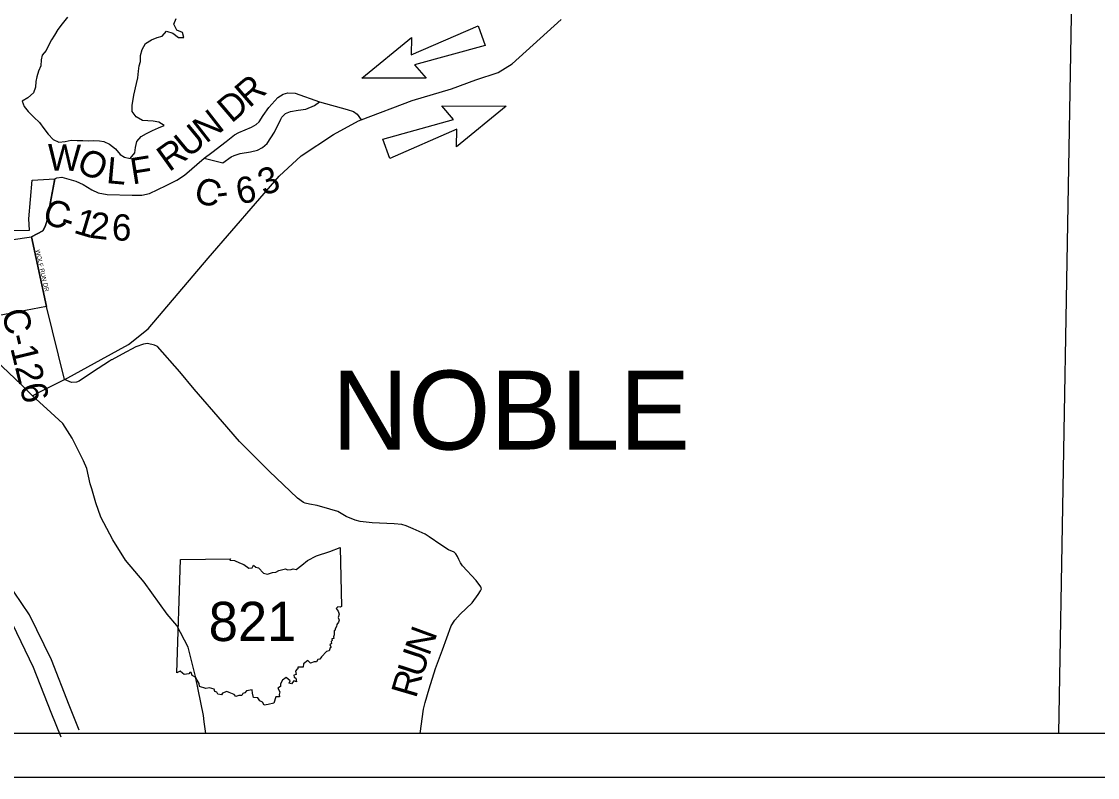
# Model space of a CAD drawing. Extents: x -452339 to 6403467, y -1 to 1814750.
# Drawn here: x -369340 to -357078, y 1603479 to 1612095 of the extents above; entities that cross this region are included whole.
import ezdxf

# ---------------------------------------------------------------- set-up
doc = ezdxf.new("R2010")
doc.units = 0
for name, color, linetype in [('Default', 7, 'Continuous'), ('GM_X_County', 7, 'Continuous'), ('GM_X_County_Road', 7, 'Continuous'), ('GM_X_Major_River', 7, 'Continuous'), ('GM_X_Minor_Lake', 7, 'Continuous'), ('GM_X_Minor_Lake_Text', 7, 'Continuous'), ('GM_X_Minor_River', 7, 'Continuous'), ('GM_X_Minor_River_Text', 7, 'Continuous'), ('GM_X_Section_Text', 7, 'Continuous'), ('GM_X_Township_Subdivision_Text', 7, 'Continuous')]:
    doc.layers.add(name, color=color, linetype=linetype)

msp = doc.modelspace()

# ---------------------------------------------------------------- linework, layer by layer
at = {"layer": 'Default'}
for p, q in [((-364900, 1611714), (-364136, 1612048)), ((-364136, 1612048), (-364057, 1611824)), ((-365463, 1611449), (-364895, 1611915)), ((-364895, 1611915), (-364900, 1611714)), ((-364057, 1611824), (-364860, 1611600)), ((-364860, 1611600), (-364728, 1611448)), ((-364728, 1611448), (-365463, 1611449)), ((-364418, 1610980), (-364550, 1611134)), ((-364550, 1611134), (-363815, 1611132)), ((-363815, 1611132), (-364383, 1610666)), ((-365221, 1610756), (-364418, 1610980)), ((-364379, 1610867), (-365142, 1610533)), ((-364383, 1610666), (-364379, 1610867)), ((-365142, 1610533), (-365221, 1610756)), ((-367572, 1604672), (-367530, 1605963)), ((-345663, 1603979), (-403040, 1603979))]:
    msp.add_line(p, q, dxfattribs=at)
msp.add_lwpolyline([(-403540, 1661857), (-345163, 1661857), (-345163, 1603479), (-403540, 1603479)], close=True, dxfattribs=at)
for points in [[(-367257, 1610538), (-367257, 1610538), (-367170, 1610602), (-367006, 1610728), (-366914, 1610804), (-366864, 1610831), (-366720, 1610893), (-366666, 1610923), (-366632, 1610953), (-366586, 1611025), (-366522, 1611117), (-366420, 1611228), (-366360, 1611266), (-366304, 1611282), (-366220, 1611278), (-365945, 1611179)], [(-367257, 1610538), (-367047, 1610484), (-366952, 1610552), (-366916, 1610568), (-366850, 1610590), (-366732, 1610610), (-366650, 1610629), (-366594, 1610661), (-366542, 1610705), (-366458, 1610833), (-366386, 1610981), (-366372, 1611005), (-366330, 1611046), (-366274, 1611068), (-366188, 1611086), (-366100, 1611098), (-366000, 1611138), (-365945, 1611179)], [(-365945, 1611179), (-365630, 1611093), (-365558, 1611071), (-365516, 1611039), (-365470, 1610976)], [(-368961, 1610301), (-368961, 1610301), (-368939, 1610313), (-368881, 1610321), (-368723, 1610277), (-368639, 1610237), (-368537, 1610177), (-368467, 1610141), (-368363, 1610125), (-368081, 1610116), (-367969, 1610116), (-367881, 1610136), (-367691, 1610227), (-367571, 1610287), (-367483, 1610345), (-367257, 1610538)], [(-368851, 1608016), (-369054, 1608849)], [(-364098, 1605628), (-364098, 1605628), (-364104, 1605654), (-364160, 1605724), (-364315, 1605892), (-364337, 1605924), (-364357, 1605964), (-364373, 1605998), (-364389, 1606028), (-364409, 1606048), (-364475, 1606074), (-364563, 1606130), (-364695, 1606222), (-364741, 1606252), (-364875, 1606314), (-364955, 1606348), (-365007, 1606362), (-365095, 1606372), (-365343, 1606383), (-365481, 1606397), (-365539, 1606411), (-365639, 1606455), (-365737, 1606509), (-365827, 1606539), (-365971, 1606581), (-366059, 1606593), (-366109, 1606607), (-366128, 1606613), (-366193, 1606664), (-366517, 1606970), (-366855, 1607308), (-367051, 1607534), (-367371, 1607904), (-367535, 1608102), (-367789, 1608392), (-367825, 1608408), (-367905, 1608426), (-367951, 1608418), (-368037, 1608388), (-368195, 1608304), (-368312, 1608239)], [(-368312, 1608239), (-368314, 1608238), (-368337, 1608225), (-368531, 1608099), (-368685, 1607996), (-368713, 1607984), (-368769, 1607980), (-368851, 1608016)], [(-367530, 1605963), (-366958, 1605971), (-366967, 1605956), (-366913, 1605952), (-366856, 1605925), (-366807, 1605907), (-366748, 1605866), (-366712, 1605867), (-366697, 1605901), (-366670, 1605875), (-366638, 1605870), (-366582, 1605808), (-366536, 1605795), (-366480, 1605816), (-366440, 1605819), (-366409, 1605840), (-366331, 1605858), (-366309, 1605847), (-366267, 1605850), (-366246, 1605858), (-366210, 1605850), (-366146, 1605898), (-366081, 1605953), (-365979, 1606005), (-365828, 1606054), (-365709, 1606099), (-365692, 1605429)], [(-364796, 1603979), (-364757, 1604258), (-364739, 1604334), (-364693, 1604490), (-364621, 1604721), (-364542, 1604935), (-364444, 1605207), (-364400, 1605274), (-364342, 1605340), (-364206, 1605468), (-364134, 1605566), (-364108, 1605606), (-364098, 1605628)], [(-365692, 1605429), (-365709, 1605419), (-365737, 1605424), (-365755, 1605405), (-365732, 1605374), (-365721, 1605340), (-365731, 1605304), (-365721, 1605274), (-365728, 1605249), (-365745, 1605223), (-365751, 1605200), (-365766, 1605174), (-365765, 1605160), (-365778, 1605149), (-365776, 1605107), (-365783, 1605084), (-365781, 1605064), (-365803, 1605059), (-365798, 1605042), (-365813, 1605029), (-365809, 1605007), (-365826, 1604993), (-365810, 1604965), (-365823, 1604956), (-365833, 1604922), (-365863, 1604915), (-365920, 1604853), (-365941, 1604829), (-365964, 1604823), (-365977, 1604799), (-366005, 1604799), (-366048, 1604782), (-366076, 1604811), (-366125, 1604776), (-366130, 1604736), (-366192, 1604737), (-366190, 1604717), (-366203, 1604711), (-366216, 1604691), (-366209, 1604654), (-366238, 1604645), (-366234, 1604624), (-366215, 1604611), (-366207, 1604571), (-366238, 1604579), (-366263, 1604545), (-366289, 1604553), (-366280, 1604582), (-366324, 1604617), (-366365, 1604589), (-366387, 1604545), (-366387, 1604515), (-366418, 1604497), (-366398, 1604455), (-366402, 1604426), (-366401, 1604398), (-366440, 1604399), (-366463, 1604325)], [(-366463, 1604325), (-366530, 1604311), (-366576, 1604303), (-366592, 1604336), (-366625, 1604354), (-366647, 1604388), (-366695, 1604392), (-366706, 1604439), (-366711, 1604477), (-366776, 1604468), (-366794, 1604444), (-366817, 1604438), (-366831, 1604415), (-366862, 1604413), (-366896, 1604402), (-366918, 1604425), (-366974, 1604448), (-366999, 1604460), (-367051, 1604441), (-367062, 1604420), (-367103, 1604429), (-367113, 1604453), (-367138, 1604461), (-367143, 1604486), (-367197, 1604500), (-367238, 1604495), (-367310, 1604515), (-367315, 1604549), (-367339, 1604590), (-367352, 1604619), (-367397, 1604641), (-367407, 1604675), (-367421, 1604674), (-367435, 1604660), (-367486, 1604654), (-367506, 1604667), (-367534, 1604691), (-367572, 1604672)]]:
    msp.add_lwpolyline(points, dxfattribs=at)
at = {"layer": 'GM_X_County_Road'}
for points in [[(-368890, 1603938), (-369003, 1604221), (-369202, 1604733), (-369441, 1605222), (-369696, 1605604), (-370132, 1606327), (-370470, 1606783), (-370794, 1607398), (-370936, 1607768), (-371013, 1608282)], [(-368685, 1604020), (-368798, 1604302), (-369000, 1604822), (-369250, 1605332), (-369510, 1605722), (-369949, 1606450), (-370284, 1606901), (-370593, 1607490), (-370722, 1607824), (-370795, 1608315)], [(-367258, 1604115), (-367268, 1604184), (-367358, 1604630), (-367441, 1604965), (-367569, 1605211), (-367680, 1605340), (-367942, 1605707), (-368154, 1605957), (-368301, 1606189), (-368438, 1606445), (-368492, 1606609), (-368539, 1606769), (-368556, 1606827), (-368596, 1607001), (-368632, 1607087), (-368762, 1607348), (-368868, 1607512), (-369051, 1607682), (-369215, 1607831)], [(-367238, 1603979), (-367258, 1604115)]]:
    msp.add_lwpolyline(points, dxfattribs=at)
at = {"layer": 'GM_X_Major_River'}
for points in [[(-369215, 1607831), (-369147, 1607868), (-368851, 1608016), (-368811, 1608036), (-368431, 1608245), (-368121, 1608414), (-367898, 1608594), (-367213, 1609399), (-366403, 1610332), (-366152, 1610565), (-365786, 1610808), (-365498, 1610965), (-365470, 1610976), (-364887, 1611195), (-364438, 1611327), (-364162, 1611429), (-363908, 1611514), (-363750, 1611615), (-363191, 1612119)], [(-369215, 1607831), (-369339, 1607955), (-369635, 1608233), (-369839, 1608443), (-369957, 1608609), (-370024, 1608752)]]:
    msp.add_lwpolyline(points, dxfattribs=at)
at = {"layer": 'GM_X_Minor_Lake'}
for points in [[(-369228, 1609643), (-369096, 1609709), (-369071, 1609761), (-369061, 1609794), (-369034, 1609879), (-369012, 1610023), (-368988, 1610160), (-368961, 1610301)], [(-369463, 1609607), (-369228, 1609643)], [(-369054, 1608849), (-369228, 1609643)]]:
    msp.add_lwpolyline(points, dxfattribs=at)
at = {"layer": 'GM_X_Minor_Lake_Text'}
for points in [[(-368815, 1612144), (-368876, 1612069), (-368926, 1612003), (-368963, 1611938), (-368997, 1611886), (-369026, 1611836), (-369061, 1611765), (-369105, 1611711), (-369116, 1611660), (-369121, 1611592), (-369145, 1611530), (-369166, 1611464), (-369178, 1611413), (-369179, 1611347), (-369204, 1611283), (-369268, 1611224), (-369331, 1611188), (-369309, 1611128), (-369294, 1611107)], [(-368034, 1611008), (-368078, 1611069), (-368081, 1611141), (-368068, 1611207), (-368060, 1611257), (-368030, 1611390), (-368016, 1611454), (-368007, 1611528), (-367998, 1611590), (-367984, 1611641), (-367983, 1611709), (-367964, 1611775), (-367926, 1611845), (-367857, 1611888), (-367795, 1611915), (-367737, 1611930), (-367686, 1611984), (-367616, 1611963), (-367553, 1611914), (-367489, 1611912), (-367506, 1611970), (-367570, 1611997), (-367603, 1612065), (-367579, 1612131)], [(-369294, 1611107), (-369266, 1611068), (-369201, 1611007), (-369137, 1610943), (-369086, 1610878), (-369035, 1610810), (-368981, 1610749), (-368915, 1610722), (-368841, 1610727), (-368775, 1610745), (-368705, 1610740), (-368643, 1610741), (-368577, 1610737), (-368523, 1610740), (-368451, 1610737), (-368401, 1610729), (-368337, 1610696), (-368270, 1610643), (-368215, 1610579), (-368165, 1610550), (-368103, 1610536), (-368050, 1610597), (-368042, 1610659), (-368027, 1610729), (-367976, 1610786), (-367914, 1610819), (-367846, 1610853), (-367779, 1610882), (-367715, 1610911), (-367777, 1610950), (-367841, 1610958), (-367901, 1610963), (-367963, 1610968), (-368034, 1611008)]]:
    msp.add_lwpolyline(points, dxfattribs=at)
at = {"layer": 'GM_X_Minor_River_Text'}
for p, q in [((-369258, 1609846), (-369217, 1610286)), ((-369217, 1610286), (-368961, 1610301)), ((-368961, 1610301), (-369003, 1610079)), ((-369003, 1610079), (-369035, 1609877)), ((-369251, 1609717), (-369258, 1609846)), ((-369035, 1609877), (-369071, 1609760)), ((-369071, 1609760), (-369096, 1609708)), ((-369665, 1609714), (-369251, 1609717)), ((-369096, 1609708), (-369228, 1609643)), ((-369228, 1609643), (-369054, 1608849)), ((-369054, 1608849), (-370270, 1608616))]:
    msp.add_line(p, q, dxfattribs=at)
at = {"layer": 'GM_X_Section_Text'}
msp.add_line((-357093, 1628200), (-357520, 1603979), dxfattribs=at)

# ---------------------------------------------------------------- texts
at = {"layer": 'Default'}
msp.add_text('821', height=447.7, dxfattribs=at).set_placement((-367207, 1605034))
at = {"layer": 'GM_X_County'}
for s, rotation, p in [('R', 40.8254, (-366745, 1611102)), ('D', 40.4787, (-366947, 1610929)), ('N', 37.9088, (-367238, 1610699)), ('U', 39.5671, (-367440, 1610532)), ('R', 35.6808, (-367658, 1610375)), ('W', 358.8739, (-369045, 1610399)), ('O', 334.3277, (-368731, 1610400)), ('L', 354.7876, (-368381, 1610255)), ('F', 9.0926, (-368076, 1610237)), ('6', 11.6746, (-366863, 1610008)), ('3', 20.3601, (-366578, 1610106)), ('C', 346.1465, (-367389, 1610040)), ('-', 6.9111, (-367103, 1610000)), ('C', 342.2019, (-369117, 1609804)), ('-', 342.3963, (-368915, 1609725)), ('1', 343.3517, (-368758, 1609690)), ('2', 353.3579, (-368577, 1609632)), ('6', 358.2651, (-368314, 1609602)), ('C-126', 283.6351, (-369569, 1608787)), ('N', 69.898, (-364695, 1604855)), ('U', 71.8254, (-364776, 1604607)), ('R', 73.6884, (-364845, 1604373))]:
    msp.add_text(s, height=300, rotation=rotation, dxfattribs=at).set_placement(p)
at = {"layer": 'GM_X_Minor_River'}
msp.add_text('WOLF RUN DR', height=50, rotation=282.8582, dxfattribs=at).set_placement((-369182, 1609489))
at = {"layer": 'GM_X_Township_Subdivision_Text'}
msp.add_text('NOBLE', height=900, rotation=0, dxfattribs=at).set_placement((-365802, 1607217))

doc.saveas('drawing.dxf')
